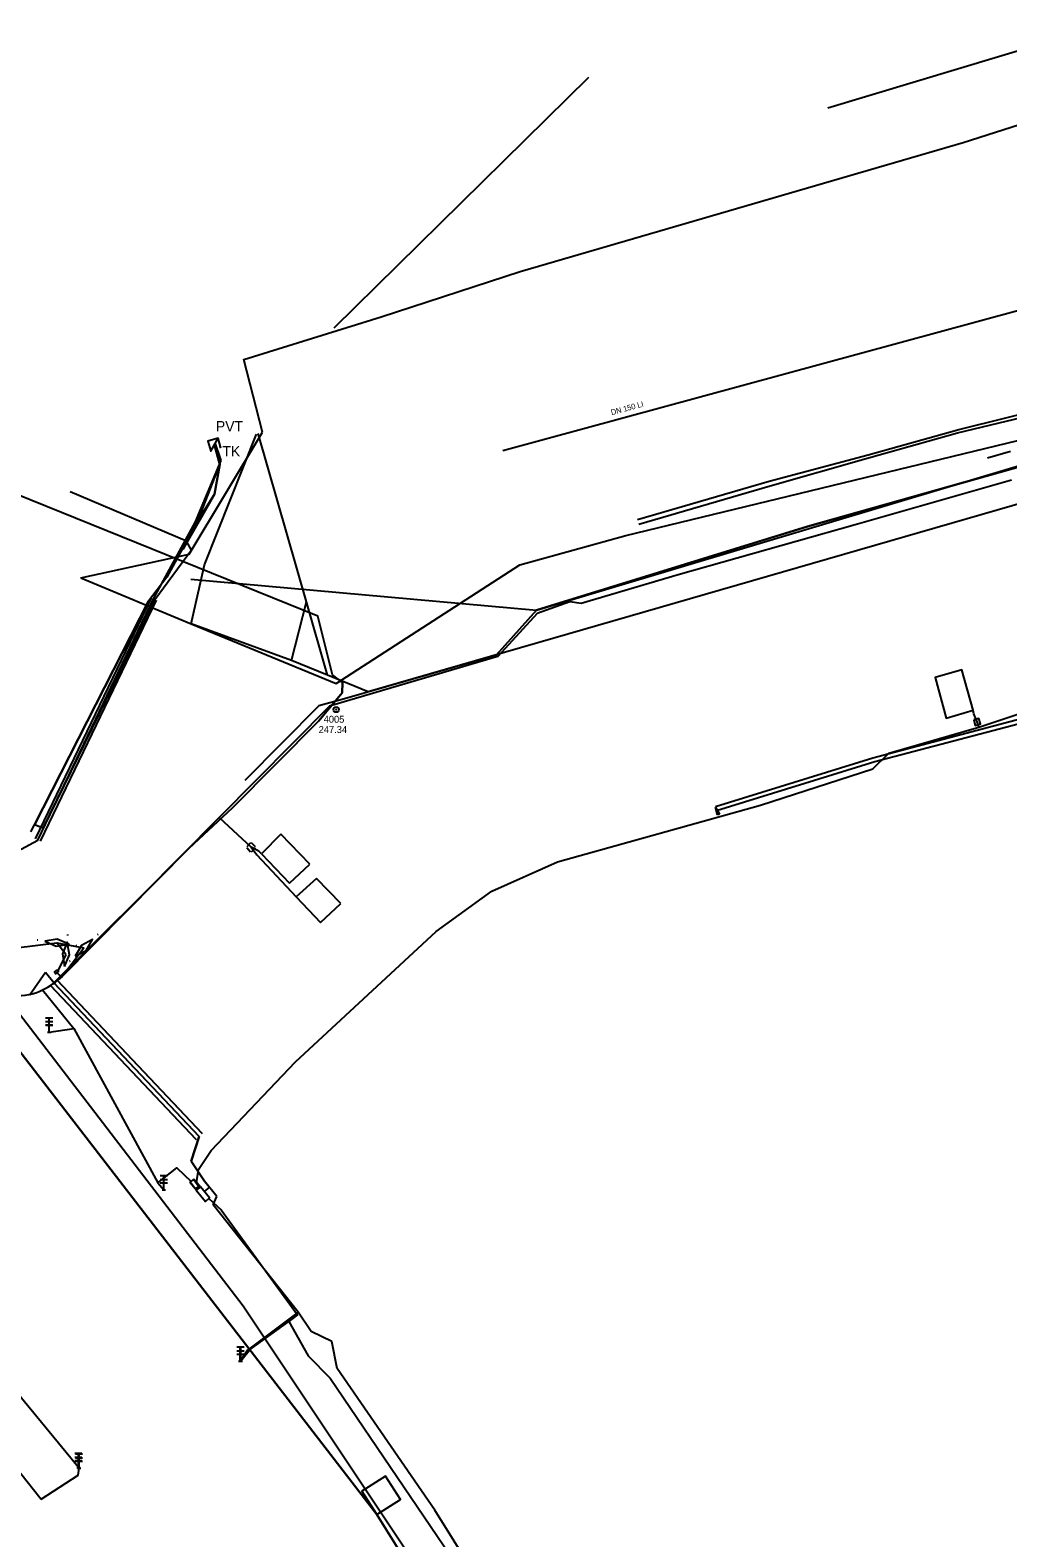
# Model space of a CAD drawing. Extents: x -599432 to -598680, y -1159407 to -1158632.
# Drawn here: x -599335.1 to -599264.7, y -1159035.2 to -1158926.7 of the extents above; entities that cross this region are included whole.
import ezdxf

# ---------------------------------------------------------------- set-up
doc = ezdxf.new("R2010")
doc.units = 0
for name, color, linetype in [('0001 VY - Body PBP', 7, 'Continuous'), ('0002 VY - Body PBP - čísla', 7, 'Continuous'), ('0003 VY - Body PBP - výšky', 7, 'Continuous'), ('0202 PV - MUNI', 7, 'Continuous'), ('0203 PV - MUNI - chránička', 7, 'Continuous'), ('0213 PV - BVK - vodovod - popis', 7, 'Continuous'), ('0214 PV - BVK - vodovod - pitná', 7, 'Continuous'), ('0354 PV - EON - VN', 7, 'Continuous'), ('0359 PV - EON - sdělovací kabely', 7, 'Continuous'), ('0367 PV - EON - VN chránička', 7, 'Continuous'), ('0407 PV - TSB - kabelové vedení přibližný zákres', 7, 'Continuous'), ('0454 PV - O2 - kabel zaměřený', 7, 'Continuous'), ('0455 PV - O2 - kabel nezaměřený', 7, 'Continuous'), ('0457 PV - O2 - kabelovod', 7, 'Continuous'), ('0530 PV - T-mobile - optické kabely', 7, 'Continuous'), ('0602 PV - FASTER', 7, 'Continuous'), ('0650 PV - BKOM - buňky', 7, 'Continuous'), ('0652 PV - BKOM - kabely bez rozlišení', 7, 'Continuous'), ('0653 PV - BKOM - chranička', 7, 'Continuous'), ('0700 PV - DIAL TELECOM - buňky', 7, 'Continuous'), ('0703 PV - DIAL TELECOM optický kabel', 7, 'Continuous')]:
    doc.layers.add(name, color=color, linetype=linetype)

# ---------------------------------------------------------------- blocks, each defined once
blk = doc.blocks.new('5.250')
at = {"layer": '0001 VY - Body PBP'}
for p, q in [((1, 4), (-1, 4)), ((-1, 3), (1, 3)), ((-1, 2), (1, 2)), ((-0.5, 0), (0.5, 0)), ((0, 0), (0, 4))]:
    blk.add_line(p, q, dxfattribs=at)

msp = doc.modelspace()

# ---------------------------------------------------------------- linework, layer by layer
at = {"layer": '0001 VY - Body PBP'}
for radius in [0.188, 0.00896]:
    msp.add_circle((-599313.06, -1158975.64), radius, dxfattribs=at)
at = {"layer": '0202 PV - MUNI'}
msp.add_line((-599321.33, -1158957.71), (-599321.77, -1158956.45), dxfattribs=at)
msp.add_lwpolyline([(-599357.23, -1159002.08), (-599346.29, -1158983.8), (-599344.78, -1158982.84), (-599342.91, -1158983.03), (-599335.72, -1158985.67), (-599334.52, -1158985.02), (-599326.19, -1158967.67), (-599323.19, -1158962.12), (-599321.33, -1158957.71)], dxfattribs=at)
at = {"layer": '0203 PV - MUNI - chránička'}
for p, q in [((-599326.37, -1158967.59), (-599334.7, -1158984.94)), ((-599326.01, -1158967.76), (-599334.34, -1158985.11))]:
    msp.add_line(p, q, dxfattribs=at)
at = {"layer": '0214 PV - BVK - vodovod - pitná'}
msp.add_lwpolyline([(-599225.27, -1158936.3), (-599245.28, -1158941.84), (-599252.5, -1158943.8), (-599301.08, -1158957.01)], dxfattribs=at)
at = {"layer": '0354 PV - EON - VN'}
for points in [[(-599291.39, -1158961.95), (-599281.92, -1158959.2), (-599274.79, -1158957.31), (-599268.27, -1158955.49), (-599261.52, -1158953.81)], [(-599291.3, -1158962.29), (-599281.84, -1158959.53), (-599274.76, -1158957.51), (-599268.36, -1158955.71), (-599261.37, -1158954.03)], [(-599262.62, -1158975.99), (-599274.45, -1158979.12), (-599285.78, -1158982.63)], [(-599262.55, -1158976.29), (-599274.31, -1158979.39), (-599285.71, -1158982.91)]]:
    msp.add_lwpolyline(points, dxfattribs=at)
at = {"layer": '0359 PV - EON - sdělovací kabely'}
msp.add_lwpolyline([(-599290.32, -1158965.9), (-599279.16, -1158962.47), (-599254.08, -1158955.38)], dxfattribs=at)
msp.add_lwpolyline([(-599290.32, -1158965.9), (-599279.16, -1158962.47), (-599254.08, -1158955.38)], dxfattribs=at)
at = {"layer": '0367 PV - EON - VN chránička'}
for p, q in [((-599285.78, -1158982.65), (-599285.49, -1158983.16)), ((-599285.63, -1158983.2), (-599285.78, -1158982.65)), ((-599285.49, -1158983.16), (-599285.63, -1158983.2))]:
    msp.add_line(p, q, dxfattribs=at)
at = {"layer": '0407 PV - TSB - kabelové vedení přibližný zákres'}
msp.add_line((-599266.2, -1158957.51), (-599264.56, -1158957.04), dxfattribs=at)
at = {"layer": '0454 PV - O2 - kabel zaměřený'}
for points in [[(-599170.95, -1158960.75), (-599171.57, -1158958.1), (-599176.08, -1158938.65), (-599176.27, -1158937.98), (-599197.19, -1158944.1), (-599211.71, -1158947.94), (-599214.99, -1158947.61), (-599219.74, -1158945.64), (-599223.26, -1158942.69), (-599223.85, -1158942.83), (-599244.1, -1158947.49), (-599244.69, -1158950.99), (-599249.7, -1158956.72), (-599251.15, -1158957.14), (-599310.75, -1158974.35), (-599313.69, -1158973.15)], [(-599331.42, -1158966.16), (-599323.64, -1158964.46), (-599318.36, -1158955.68)], [(-599323.5, -1158969.46), (-599313.05, -1158973.75), (-599299.85, -1158965.21), (-599292.23, -1158963.1), (-599261.66, -1158955.7)], [(-599323.5, -1158969.46), (-599322.52, -1158965.21), (-599318.8, -1158955.81)], [(-599315.2, -1158967.89), (-599318.66, -1158955.77)], [(-599323.82, -1158963.52), (-599322.99, -1158962), (-599321.42, -1158957.99), (-599321.79, -1158956.68)], [(-599323.82, -1158963.52), (-599332.19, -1158959.96)], [(-599323.82, -1158963.52), (-599325.23, -1158966.1), (-599326.56, -1158967.84), (-599334.76, -1158983.93)], [(-599323.46, -1158964.16), (-599326.16, -1158967.81), (-599334.13, -1158984.16), (-599334.76, -1158983.93)], [(-599331.42, -1158966.16), (-599323.5, -1158969.46)], [(-599335.02, -1158984.43), (-599334.76, -1158983.93), (-599326.56, -1158967.84)], [(-599334.13, -1158984.16), (-599326.16, -1158967.81)], [(-599316.28, -1158972.09), (-599315.2, -1158967.89)], [(-599313.69, -1158973.15), (-599315.2, -1158967.89)], [(-599316.28, -1158972.09), (-599323.5, -1158969.46)], [(-599313.69, -1158973.15), (-599316.28, -1158972.09)], [(-599339.07, -1158993.32), (-599319.74, -1159018.55), (-599300.29, -1159047.75), (-599295.69, -1159055.6)]]:
    msp.add_lwpolyline(points, dxfattribs=at)
at = {"layer": '0455 PV - O2 - kabel nezaměřený'}
for points in [[(-599255.99, -1158937.12), (-599259.03, -1158926.74), (-599277.69, -1158932.36)], [(-599267.95, -1158934.82), (-599258.65, -1158931.86), (-599255.99, -1158937.12)], [(-599299.83, -1158944.12), (-599267.95, -1158934.82)], [(-599309.82, -1158947.37), (-599299.83, -1158944.12)], [(-599318.36, -1158955.68), (-599319.71, -1158950.44), (-599309.82, -1158947.37)], [(-599323.46, -1158964.16), (-599323.82, -1158963.52)], [(-599277.08, -1159086.72), (-599310.13, -1159033.56), (-599337.19, -1158998.47), (-599375, -1158964.86)]]:
    msp.add_lwpolyline(points, dxfattribs=at)
at = {"layer": '0457 PV - O2 - kabelovod'}
msp.add_lwpolyline([(-599375, -1158964.86), (-599337.19, -1158998.47), (-599310.13, -1159033.56), (-599277.08, -1159086.72), (-599234.14, -1159160.34), (-599189.54, -1159237.04), (-599142.76, -1159320.34), (-599091.04, -1159406.68)], dxfattribs=at)
msp.add_lwpolyline([(-599310.13, -1159033.56), (-599308.44, -1159032.48), (-599309.52, -1159030.8), (-599311.21, -1159031.87)], close=True, dxfattribs=at)
at = {"layer": '0530 PV - T-mobile - optické kabely'}
msp.add_lwpolyline([(-599294.92, -1158930.15), (-599313.22, -1158948.19)], dxfattribs=at)
at = {"layer": '0602 PV - FASTER'}
for points in [[(-599323.51, -1158966.26), (-599298.66, -1158968.47), (-599253.49, -1158954.94), (-599252.93, -1158950.8), (-599250.35, -1158946.57), (-599248.8, -1158945.94), (-599249.17, -1158942.79), (-599250.58, -1158936.8)], [(-599324.1, -1158964.03), (-599322.99, -1158962), (-599321.8, -1158960.14), (-599321.42, -1158957.99), (-599321.82, -1158956.57)], [(-599321.82, -1158956.57), (-599321.42, -1158957.99), (-599321.8, -1158960.14), (-599324.08, -1158964.11)]]:
    msp.add_lwpolyline(points, dxfattribs=at)
at = {"layer": '0650 PV - BKOM - buňky'}
for p, q in [((-599319.21, -1158985.22), (-599319.49, -1158985.5)), ((-599319.49, -1158985.57), (-599319.21, -1158985.86)), ((-599318.86, -1158985.5), (-599319.14, -1158985.22)), ((-599319.14, -1158985.86), (-599318.86, -1158985.57)), ((-599334.52, -1158992.23), (-599334.57, -1158992.22)), ((-599332.36, -1158991.88), (-599332.36, -1158991.83)), ((-599331.79, -1158992.59), (-599331.74, -1158992.6)), ((-599330.22, -1158991.83), (-599330.18, -1158991.79)), ((-599332.2, -1158993.73), (-599332.24, -1158993.76)), ((-599332.64, -1158994.62), (-599332.65, -1158994.67)), ((-599333.46, -1158997.83), (-599333.96, -1158997.83)), ((-599333.46, -1158997.83), (-599333.96, -1158997.83)), ((-599333.96, -1158998.08), (-599333.46, -1158998.08)), ((-599333.96, -1158998.08), (-599333.46, -1158998.08)), ((-599333.71, -1158998.83), (-599333.71, -1158997.83)), ((-599333.71, -1158998.83), (-599333.71, -1158997.83)), ((-599333.96, -1158998.33), (-599333.46, -1158998.33)), ((-599333.96, -1158998.33), (-599333.46, -1158998.33)), ((-599325.2, -1159009.19), (-599325.7, -1159009.19)), ((-599325.2, -1159009.19), (-599325.7, -1159009.19)), ((-599325.7, -1159009.44), (-599325.2, -1159009.44)), ((-599325.7, -1159009.44), (-599325.2, -1159009.44)), ((-599325.7, -1159009.69), (-599325.2, -1159009.69)), ((-599325.7, -1159009.69), (-599325.2, -1159009.69)), ((-599325.45, -1159010.19), (-599325.45, -1159009.19)), ((-599325.45, -1159010.19), (-599325.45, -1159009.19)), ((-599325.58, -1159010.19), (-599325.33, -1159010.19)), ((-599325.58, -1159010.19), (-599325.33, -1159010.19)), ((-599319.71, -1159021.52), (-599320.21, -1159021.52)), ((-599320.21, -1159021.77), (-599319.71, -1159021.77)), ((-599319.96, -1159022.52), (-599319.96, -1159021.52)), ((-599320.21, -1159022.02), (-599319.71, -1159022.02)), ((-599320.08, -1159022.52), (-599319.83, -1159022.52)), ((-599331.35, -1159029.17), (-599331.85, -1159029.17)), ((-599331.85, -1159029.42), (-599331.35, -1159029.42)), ((-599331.6, -1159030.17), (-599331.6, -1159029.17)), ((-599331.85, -1159029.67), (-599331.35, -1159029.67)), ((-599331.72, -1159030.17), (-599331.47, -1159030.17))]:
    msp.add_line(p, q, dxfattribs=at)
for points in [[(-599267.2, -1158976.38), (-599267.09, -1158976.77), (-599266.7, -1158976.65), (-599266.82, -1158976.27)], [(-599334.02, -1158992.29), (-599333.19, -1158992.66), (-599332.29, -1158992.52), (-599333.12, -1158992.16)], [(-599332.59, -1158994.12), (-599332.25, -1158993.28), (-599332.41, -1158992.38), (-599332.75, -1158993.22)], [(-599331.84, -1158993.38), (-599331.04, -1158992.96), (-599330.58, -1158992.18), (-599331.38, -1158992.6)], [(-599333.13, -1158994.36), (-599333.33, -1158994.51), (-599333.22, -1158994.65), (-599333.03, -1158994.49)], [(-599323.29, -1159009.42), (-599323.57, -1159009.66), (-599323.17, -1159010.13), (-599322.87, -1159009.91)], [(-599323.29, -1159009.46), (-599322.93, -1159009.96), (-599323.19, -1159010.15), (-599323.55, -1159009.65)], [(-599322.82, -1159009.97), (-599323.12, -1159010.21), (-599322.46, -1159011.03), (-599322.17, -1159010.78)]]:
    msp.add_lwpolyline(points, close=True, dxfattribs=at)
at = {"layer": '0652 PV - BKOM - kabely bez rozlišení'}
for p, q in [((-599264.49, -1158959.12), (-599275.72, -1158962.34)), ((-599275.72, -1158962.34), (-599288.45, -1158965.93)), ((-599288.45, -1158965.93), (-599295.44, -1158967.99)), ((-599298.6, -1158968.71), (-599301.44, -1158971.82)), ((-599296.25, -1158967.89), (-599298.6, -1158968.71)), ((-599295.44, -1158967.99), (-599296.25, -1158967.89)), ((-599301.44, -1158971.82), (-599313.55, -1158975.38)), ((-599313.55, -1158975.38), (-599321.48, -1158983.41)), ((-599326.96, -1158988.93), (-599321.48, -1158983.41)), ((-599321.48, -1158983.41), (-599326.96, -1158988.93)), ((-599321.48, -1158983.41), (-599319.18, -1158985.54)), ((-599317.04, -1158984.59), (-599318.44, -1158986.02)), ((-599314.96, -1158986.77), (-599317.04, -1158984.59)), ((-599318.63, -1158985.83), (-599319.18, -1158985.54)), ((-599319.18, -1158985.54), (-599318.76, -1158986.08)), ((-599318.76, -1158986.08), (-599315.93, -1158989.11)), ((-599318.44, -1158986.02), (-599318.63, -1158985.83)), ((-599318.44, -1158986.02), (-599316.42, -1158988.12)), ((-599316.42, -1158988.12), (-599314.96, -1158986.77)), ((-599314.48, -1158987.8), (-599315.93, -1158989.11)), ((-599312.72, -1158989.59), (-599314.48, -1158987.8)), ((-599333.38, -1158995.29), (-599326.96, -1158988.93)), ((-599326.96, -1158988.93), (-599333.38, -1158995.29)), ((-599315.93, -1158989.11), (-599314.18, -1158990.95)), ((-599314.18, -1158990.95), (-599312.72, -1158989.59)), ((-599336.07, -1158992.79), (-599333.16, -1158992.41)), ((-599336.07, -1158992.79), (-599333.16, -1158992.41)), ((-599333.16, -1158992.41), (-599331.21, -1158992.78)), ((-599332.5, -1158993.25), (-599333.16, -1158992.41)), ((-599333.16, -1158992.41), (-599331.21, -1158992.78)), ((-599332.5, -1158993.25), (-599333.16, -1158992.41)), ((-599332.5, -1158993.25), (-599333.08, -1158994.43)), ((-599332.5, -1158993.25), (-599333.08, -1158994.43)), ((-599332.82, -1158994.89), (-599331.21, -1158992.78)), ((-599332.82, -1158994.89), (-599331.21, -1158992.78)), ((-599333.97, -1158994.55), (-599335.12, -1158996.2)), ((-599333.38, -1158995.29), (-599333.97, -1158994.55)), ((-599333.12, -1158994.57), (-599332.82, -1158994.89)), ((-599333.12, -1158994.57), (-599332.82, -1158994.89)), ((-599322.92, -1159006.36), (-599333.38, -1158995.29)), ((-599333.38, -1158995.29), (-599322.92, -1159006.36)), ((-599333.7, -1158998.84), (-599331.92, -1158998.59)), ((-599323.5, -1159008.14), (-599322.92, -1159006.36)), ((-599322.92, -1159006.36), (-599323.5, -1159008.14)), ((-599322.53, -1159009.57), (-599323.5, -1159008.14)), ((-599323.5, -1159008.14), (-599322.53, -1159009.57)), ((-599325.88, -1159009.69), (-599325.46, -1159010.19)), ((-599323.03, -1159010.03), (-599322.96, -1159010.08)), ((-599322.18, -1159010.01), (-599322.56, -1159010.32)), ((-599321.64, -1159010.68), (-599322.53, -1159009.57)), ((-599321.91, -1159011.27), (-599321.64, -1159010.68)), ((-599315.79, -1159018.99), (-599321.91, -1159011.27)), ((-599315.79, -1159018.99), (-599319.43, -1159021.72)), ((-599319.23, -1159021.65), (-599316.47, -1159019.67)), ((-599314.85, -1159020.4), (-599315.79, -1159018.99)), ((-599313.36, -1159021.1), (-599314.85, -1159020.4)), ((-599319.43, -1159021.72), (-599319.96, -1159022.52)), ((-599319.23, -1159021.65), (-599319.92, -1159022.52)), ((-599312.98, -1159023.05), (-599313.36, -1159021.1)), ((-599305.96, -1159033.24), (-599312.98, -1159023.05)), ((-599331.6, -1159030.17), (-599336.02, -1159024.78)), ((-599301.72, -1159040.02), (-599305.96, -1159033.24))]:
    msp.add_line(p, q, dxfattribs=at)
for points in [[(-599332.75, -1158994.81), (-599323.63, -1158985.6), (-599320.52, -1158982.71), (-599314.3, -1158976.44), (-599312.63, -1158974.42), (-599312.61, -1158973.68), (-599313.32, -1158973.13), (-599314.38, -1158968.9), (-599340.48, -1158958.36), (-599355.13, -1158952.33), (-599353.44, -1158948.07), (-599352.94, -1158946.93), (-599354.01, -1158945.75)], [(-599407.48, -1158959.45), (-599409.63, -1158963.02), (-599404.92, -1158965.87), (-599392.39, -1158974.99), (-599377.54, -1158987.45), (-599362.26, -1159000.61), (-599355.46, -1159007.23), (-599352.19, -1159010.56), (-599348.22, -1159015.17), (-599341.89, -1159022.89), (-599334.28, -1159032.46)], [(-599266.84, -1158976.9), (-599266.95, -1158976.52), (-599267.18, -1158975.94), (-599267.24, -1158975.68), (-599268.06, -1158972.78), (-599269.97, -1158973.32), (-599269.17, -1158976.25), (-599267.24, -1158975.68)], [(-599323.11, -1159009.71), (-599322.96, -1159008.72), (-599322.05, -1159007.36), (-599315.99, -1159000.98), (-599305.87, -1158991.6), (-599301.86, -1158988.69), (-599297.14, -1158986.59), (-599282.53, -1158982.51), (-599274.45, -1158979.89), (-599273.31, -1158978.78), (-599266.84, -1158976.9), (-599260.99, -1158974.96)], [(-599334.18, -1158995.81), (-599331.92, -1158998.59), (-599325.88, -1159009.69), (-599324.52, -1159008.6), (-599323.48, -1159009.59)], [(-599322.53, -1159009.57), (-599322.18, -1159010.01), (-599322.56, -1159010.32)], [(-599322.21, -1159010.81), (-599321.34, -1159011.64), (-599315.83, -1159019.19), (-599316.47, -1159019.67), (-599315.07, -1159022.15), (-599313.49, -1159023.75), (-599302.89, -1159039.38), (-599292.84, -1159055.74), (-599281.17, -1159075.14), (-599285.31, -1159077.65)], [(-599334.28, -1159032.46), (-599331.62, -1159030.73), (-599331.55, -1159030.22)]]:
    msp.add_lwpolyline(points, dxfattribs=at)
for centre, radius, start, end in [((-599336.8, -1158990.48), 5.94, 296.1677, 312.904), ((-599335.97, -1158992.08), 4.14, 237.7832, 295.6351)]:
    msp.add_arc(centre, radius, start, end, dxfattribs=at)
at = {"layer": '0653 PV - BKOM - chranička'}
for p, q in [((-599323.14, -1159006.57), (-599333.6, -1158995.5)), ((-599333.6, -1158995.5), (-599323.14, -1159006.57)), ((-599322.7, -1159006.15), (-599333.16, -1158995.08)), ((-599333.16, -1158995.08), (-599322.7, -1159006.15)), ((-599331.92, -1158998.59), (-599325.88, -1159009.69))]:
    msp.add_line(p, q, dxfattribs=at)
msp.add_lwpolyline([(-599312.61, -1158973.68), (-599312.63, -1158974.42), (-599314.3, -1158976.44), (-599320.52, -1158982.71)], dxfattribs=at)
at = {"layer": '0700 PV - DIAL TELECOM - buňky'}
msp.add_lwpolyline([(-599321.35, -1158956.83), (-599321.55, -1158956.1), (-599322.28, -1158956.31), (-599322.07, -1158957.03), (-599321.55, -1158956.1)], dxfattribs=at)
at = {"layer": '0703 PV - DIAL TELECOM optický kabel'}
for points in [[(-599207.11, -1158930.84), (-599209.49, -1158932.25), (-599212.14, -1158935.06), (-599247.7, -1158945.87), (-599249.33, -1158946.19), (-599250.35, -1158946.57), (-599252.93, -1158950.8), (-599253.3, -1158954.3), (-599253.49, -1158954.94), (-599254.08, -1158955.38), (-599279.16, -1158962.47), (-599298.66, -1158968.47), (-599301.55, -1158971.73), (-599312.63, -1158974.92), (-599314.3, -1158975.37), (-599319.63, -1158980.74)], [(-599324.1, -1158964.03), (-599322.99, -1158962), (-599321.42, -1158957.99), (-599321.82, -1158956.57)]]:
    msp.add_lwpolyline(points, dxfattribs=at)

# ---------------------------------------------------------------- block references
at = {"layer": '0650 PV - BKOM - buňky', "xscale": 0.25, "yscale": 0.25}
for p in [(-599333.7, -1158998.84), (-599325.46, -1159010.19), (-599319.92, -1159022.52), (-599331.55, -1159030.22)]:
    msp.add_blockref('5.250', p, dxfattribs=at)

# ---------------------------------------------------------------- texts
at = {"layer": '0002 VY - Body PBP - čísla'}
msp.add_text('4005', height=0.5, dxfattribs=at).set_placement((-599313.96, -1158976.58))
at = {"layer": '0003 VY - Body PBP - výšky'}
msp.add_text('247.34', height=0.5, dxfattribs=at).set_placement((-599314.32, -1158977.32))
at = {"layer": '0213 PV - BVK - vodovod - popis'}
msp.add_text('DN 150 LI', height=0.4, rotation=15.1834, dxfattribs=at).set_placement((-599293.24, -1158954.45))
at = {"layer": '0700 PV - DIAL TELECOM - buňky'}
for s, p in [('PVT', (-599321.71, -1158955.62)), ('TK', (-599321.24, -1158957.42))]:
    msp.add_text(s, height=0.75, dxfattribs=at).set_placement(p)

doc.saveas('drawing.dxf')
